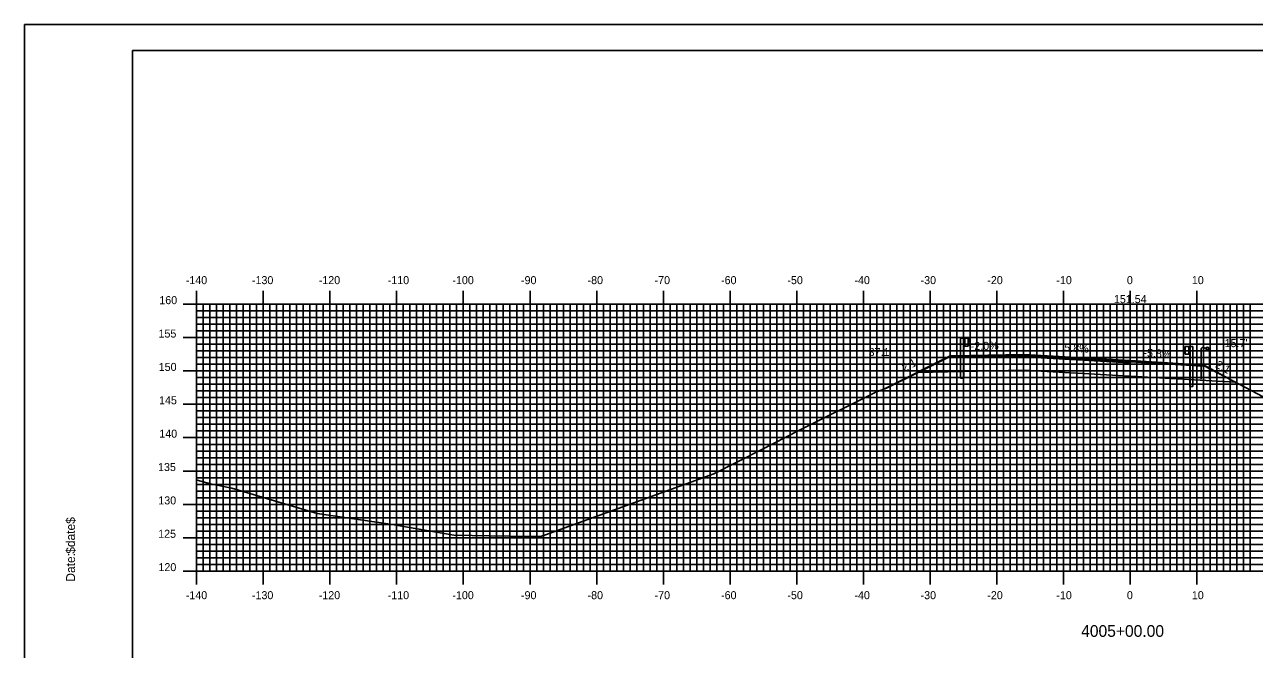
# Model space of a CAD drawing. Extents: x 850966 to 851310, y 364661 to 364881.
# Drawn here: x 850966.4 to 851150.9, y 364787.7 to 364881.3 of the extents above; entities that cross this region are included whole.
import ezdxf

# ---------------------------------------------------------------- set-up
doc = ezdxf.new("R2010")
doc.units = 0
for name, color, linetype in [('ANNOTATION', 7, 'Continuous'), ('BORDER', 7, 'Continuous'), ('D_Guardrail_Beam_Lt', 7, 'Continuous'), ('D_Guardrail_Beam_Rt', 7, 'Continuous'), ('D_Roadway_Centerline_Text', 7, 'Continuous'), ('D_Roadway_Edge_Shoulder', 7, 'Continuous'), ('D_Roadway_Edge_TW', 7, 'Continuous'), ('D_Roadway_Pavement', 7, 'Continuous'), ('D_Roadway_SlopeLines', 7, 'Continuous'), ('D_Roadway_SubGrade', 7, 'Continuous'), ('D_Text_Standard', 7, 'Continuous'), ('H_V ANNOTATION', 7, 'Continuous'), ('M_Roadway_Centerline', 7, 'Continuous'), ('M_Utilities_Pole_StreetLight', 7, 'Continuous'), ('MAJOR', 7, 'Continuous'), ('MINOR', 7, 'Continuous'), ('PLOT BOUNDARY', 7, 'Continuous'), ('S_Roadway_Centerline', 7, 'Continuous')]:
    doc.layers.add(name, color=color, linetype=linetype)

msp = doc.modelspace()

# ---------------------------------------------------------------- linework, layer by layer
at = {"layer": 'BORDER'}
msp.add_lwpolyline([(850982.62, 364667.37), (851302.62, 364667.37), (851302.62, 364877.37), (850982.62, 364877.37)], close=True, dxfattribs=at)
at = {"layer": 'D_Guardrail_Beam_Lt'}
for p, q in [((851106.79, 364834.26), (851106.79, 364828.26)), ((851107.26, 364834.26), (851106.79, 364834.26)), ((851107.94, 364834.26), (851107.26, 364834.26)), ((851107.26, 364834.26), (851107.26, 364833.09)), ((851107.32, 364834.26), (851107.32, 364833.09)), ((851107.42, 364834.26), (851107.42, 364833.09)), ((851107.94, 364833.09), (851107.94, 364834.26)), ((851107.94, 364834.18), (851108.02, 364834.16)), ((851107.95, 364833.71), (851107.95, 364833.64)), ((851108.18, 364833.91), (851107.98, 364833.78)), ((851108.03, 364834.16), (851108.18, 364834.06)), ((851107.26, 364833.09), (851107.94, 364833.09)), ((851107.28, 364828.26), (851107.28, 364833.09)), ((851108.02, 364833.19), (851107.94, 364833.18)), ((851107.98, 364833.58), (851108.18, 364833.44)), ((851108.18, 364833.3), (851108.03, 364833.2)), ((851107.28, 364828.26), (851106.79, 364828.26))]:
    msp.add_line(p, q, dxfattribs=at)
for centre, major_axis, start_param, end_param in [((851108.03, 364833.71), (-0.0789, 0), 5.323254, 6.283185), ((851108.03, 364833.64), (-0.0789, 0), 6.283185, 7.243116), ((851108.01, 364834.12), (0.0417, 0), 0.959931, 1.376053), ((851108.13, 364833.98), (0.0877, 0), 5.323254, 7.243116), ((851108.01, 364833.23), (0.0417, 0), 4.907132, 5.323254), ((851108.13, 364833.37), (0.0877, 0), 5.323254, 7.243116)]:
    msp.add_ellipse(centre, major_axis=major_axis, ratio=0.995501, start_param=start_param, end_param=end_param, dxfattribs=at)
at = {"layer": 'D_Guardrail_Beam_Rt'}
for p, q in [((851140.4, 364832.92), (851140.25, 364832.82)), ((851140.25, 364832.68), (851140.45, 364832.54)), ((851140.45, 364832.35), (851140.25, 364832.21)), ((851140.25, 364832.07), (851140.4, 364831.97)), ((851140.49, 364832.95), (851140.41, 364832.93)), ((851140.41, 364831.96), (851140.49, 364831.95)), ((851140.48, 364832.48), (851140.48, 364832.41)), ((851140.49, 364833.03), (851141.17, 364833.03)), ((851140.49, 364831.86), (851140.49, 364833.03)), ((851141.17, 364831.86), (851140.49, 364831.86)), ((851141.01, 364833.03), (851141.01, 364831.86)), ((851141.11, 364833.03), (851141.11, 364831.86)), ((851141.15, 364827.03), (851141.15, 364831.86)), ((851141.17, 364833.03), (851141.64, 364833.03)), ((851141.17, 364833.03), (851141.17, 364831.86)), ((851141.64, 364833.03), (851141.64, 364827.03)), ((851141.15, 364827.03), (851141.64, 364827.03))]:
    msp.add_line(p, q, dxfattribs=at)
for centre, major_axis, start_param, end_param in [((851140.3, 364832.75), (-0.0877, 0), 5.323254, 7.243116), ((851140.3, 364832.14), (-0.0877, 0), 5.323254, 7.243116), ((851140.42, 364832.89), (-0.0417, 0), 4.907132, 5.323254), ((851140.42, 364832), (-0.0417, 0), 0.959931, 1.376053), ((851140.4, 364832.48), (0.0789, 0), 0, 0.959931), ((851140.4, 364832.41), (0.0789, 0), 5.323254, 6.283185)]:
    msp.add_ellipse(centre, major_axis=major_axis, ratio=0.995501, start_param=start_param, end_param=end_param, dxfattribs=at)
at = {"layer": 'D_Roadway_Edge_Shoulder'}
for points in [[(851116.22, 364831.84), (851108.22, 364831.68), (851108.22, 364831.68), (851105.22, 364831.62), (851105.22, 364831.45), (851116.22, 364831.64)], [(851132.22, 364830.91), (851140.22, 364830.45), (851140.22, 364830.45), (851143.22, 364830.27), (851143.22, 364830.1), (851132.22, 364830.74)]]:
    msp.add_lwpolyline(points, close=True, dxfattribs=at)
at = {"layer": 'D_Roadway_Edge_TW'}
msp.add_lwpolyline([(851116.22, 364831.84), (851132.22, 364830.91), (851132.22, 364830.74), (851116.22, 364831.64)], close=True, dxfattribs=at)
at = {"layer": 'D_Roadway_Pavement'}
msp.add_lwpolyline([(851116.22, 364831.64), (851132.22, 364830.74), (851132.22, 364830.58), (851116.22, 364831.47)], close=True, dxfattribs=at)
for points in [[(851116.22, 364831.64), (851116.22, 364831.47)], [(851132.22, 364830.74), (851132.22, 364830.58)], [(851132.22, 364830.74), (851132.22, 364830.58)], [(851132.22, 364830.74), (851132.22, 364830.58)]]:
    msp.add_lwpolyline(points, dxfattribs=at)
at = {"layer": 'D_Roadway_SlopeLines'}
msp.add_lwpolyline([(851105.22, 364831.62), (851095.16, 364826.59)], dxfattribs=at)
at = {"layer": 'D_Roadway_SubGrade'}
msp.add_line((851143.22, 364830.27), (851147.95, 364827.69), dxfattribs=at)
for points in [[(851116.22, 364831.47), (851116.22, 364831.64), (851105.22, 364831.45), (851105.22, 364831.62), (851100.29, 364829.15), (851116.22, 364829.47)], [(851116.22, 364831.47), (851132.22, 364830.58), (851132.22, 364828.58), (851116.22, 364829.47)]]:
    msp.add_lwpolyline(points, close=True, dxfattribs=at)
msp.add_lwpolyline([(851147.95, 364827.69), (851132.22, 364828.58), (851132.22, 364830.58), (851132.22, 364830.74), (851143.22, 364830.1), (851143.22, 364830.27)], dxfattribs=at)
at = {"layer": 'M_Utilities_Pole_StreetLight'}
for p, q in [((851142.87, 364832.75), (851143.03, 364832.86)), ((851142.87, 364828.13), (851142.87, 364832.75)), ((851143.34, 364832.86), (851143.49, 364832.75)), ((851143.65, 364832.86), (851143.49, 364832.75)), ((851143.49, 364832.75), (851143.65, 364832.64)), ((851144.12, 364832.75), (851143.96, 364832.86)), ((851143.96, 364832.64), (851144.12, 364832.75)), ((851144.12, 364828.13), (851144.12, 364832.75))]:
    msp.add_line(p, q, dxfattribs=at)
for centre, start, end in [((851143.18, 364832.64), 90, 125.2644), ((851143.18, 364832.64), 54.7356, 90), ((851143.81, 364832.64), 90, 125.2644), ((851143.81, 364832.86), 234.7356, 270), ((851143.81, 364832.64), 54.7356, 90), ((851143.81, 364832.86), 270, 305.2644)]:
    msp.add_arc(centre, 0.271, start, end, dxfattribs=at)
at = {"layer": 'MAJOR'}
for p, q in [((850992.22, 364841.37), (850992.22, 364839.37)), ((851002.22, 364841.37), (851002.22, 364839.37)), ((851012.22, 364841.37), (851012.22, 364839.37)), ((851022.22, 364841.37), (851022.22, 364839.37)), ((851032.22, 364841.37), (851032.22, 364839.37)), ((851042.22, 364841.37), (851042.22, 364839.37)), ((851052.22, 364841.37), (851052.22, 364839.37)), ((851062.22, 364841.37), (851062.22, 364839.37)), ((851072.22, 364841.37), (851072.22, 364839.37)), ((851082.22, 364841.37), (851082.22, 364839.37)), ((851092.22, 364841.37), (851092.22, 364839.37)), ((851102.22, 364841.37), (851102.22, 364839.37)), ((851112.22, 364841.37), (851112.22, 364839.37)), ((851122.22, 364841.37), (851122.22, 364839.37)), ((851132.22, 364841.37), (851132.22, 364839.37)), ((851142.22, 364841.37), (851142.22, 364839.37)), ((850990.21, 364839.37), (850992.22, 364839.37)), ((850992.22, 364839.37), (851272.22, 364839.37)), ((850992.22, 364799.37), (850992.22, 364839.37)), ((850992.22, 364799.37), (850992.22, 364839.37)), ((850992.22, 364839.37), (851272.22, 364839.37)), ((851002.22, 364799.37), (851002.22, 364839.37)), ((851012.22, 364799.37), (851012.22, 364839.37)), ((851022.22, 364799.37), (851022.22, 364839.37)), ((851032.22, 364799.37), (851032.22, 364839.37)), ((851042.22, 364799.37), (851042.22, 364839.37)), ((851052.22, 364799.37), (851052.22, 364839.37)), ((851062.22, 364799.37), (851062.22, 364839.37)), ((851072.22, 364799.37), (851072.22, 364839.37)), ((851082.22, 364799.37), (851082.22, 364839.37)), ((851092.22, 364799.37), (851092.22, 364839.37)), ((851102.22, 364799.37), (851102.22, 364839.37)), ((851112.22, 364799.37), (851112.22, 364839.37)), ((851122.22, 364799.37), (851122.22, 364839.37)), ((851132.22, 364799.37), (851132.22, 364839.37)), ((851142.22, 364799.37), (851142.22, 364839.37)), ((850990.21, 364834.37), (850992.22, 364834.37)), ((850992.22, 364834.37), (851272.22, 364834.37)), ((850990.21, 364829.37), (850992.22, 364829.37)), ((850992.22, 364829.37), (851272.22, 364829.37)), ((850990.21, 364824.37), (850992.22, 364824.37)), ((850992.22, 364824.37), (851272.22, 364824.37)), ((850990.21, 364819.37), (850992.22, 364819.37)), ((850992.22, 364819.37), (851272.22, 364819.37)), ((850990.21, 364814.37), (850992.22, 364814.37)), ((850992.22, 364814.37), (851272.22, 364814.37)), ((850990.21, 364809.37), (850992.22, 364809.37)), ((850992.22, 364809.37), (851272.22, 364809.37)), ((850990.21, 364804.37), (850992.22, 364804.37)), ((850992.22, 364804.37), (851272.22, 364804.37)), ((850990.21, 364799.37), (850992.22, 364799.37)), ((850992.22, 364799.37), (851272.22, 364799.37)), ((850992.22, 364799.37), (851272.22, 364799.37)), ((850992.22, 364797.37), (850992.22, 364799.37)), ((851002.22, 364797.37), (851002.22, 364799.37)), ((851012.22, 364797.37), (851012.22, 364799.37)), ((851022.22, 364797.37), (851022.22, 364799.37)), ((851032.22, 364797.37), (851032.22, 364799.37)), ((851042.22, 364797.37), (851042.22, 364799.37)), ((851052.22, 364797.37), (851052.22, 364799.37)), ((851062.22, 364797.37), (851062.22, 364799.37)), ((851072.22, 364797.37), (851072.22, 364799.37)), ((851082.22, 364797.37), (851082.22, 364799.37)), ((851092.22, 364797.37), (851092.22, 364799.37)), ((851102.22, 364797.37), (851102.22, 364799.37)), ((851112.22, 364797.37), (851112.22, 364799.37)), ((851122.22, 364797.37), (851122.22, 364799.37)), ((851132.22, 364797.37), (851132.22, 364799.37)), ((851142.22, 364797.37), (851142.22, 364799.37))]:
    msp.add_line(p, q, dxfattribs=at)
at = {"layer": 'MINOR'}
for p, q in [((850993.22, 364799.37), (850993.22, 364839.37)), ((850994.22, 364799.37), (850994.22, 364839.37)), ((850995.22, 364799.37), (850995.22, 364839.37)), ((850996.22, 364799.37), (850996.22, 364839.37)), ((850997.22, 364799.37), (850997.22, 364839.37)), ((850998.22, 364799.37), (850998.22, 364839.37)), ((850999.22, 364799.37), (850999.22, 364839.37)), ((851000.22, 364799.37), (851000.22, 364839.37)), ((851001.22, 364799.37), (851001.22, 364839.37)), ((851003.22, 364799.37), (851003.22, 364839.37)), ((851004.22, 364799.37), (851004.22, 364839.37)), ((851005.22, 364799.37), (851005.22, 364839.37)), ((851006.22, 364799.37), (851006.22, 364839.37)), ((851007.22, 364799.37), (851007.22, 364839.37)), ((851008.22, 364799.37), (851008.22, 364839.37)), ((851009.22, 364799.37), (851009.22, 364839.37)), ((851010.22, 364799.37), (851010.22, 364839.37)), ((851011.22, 364799.37), (851011.22, 364839.37)), ((851013.22, 364799.37), (851013.22, 364839.37)), ((851014.22, 364799.37), (851014.22, 364839.37)), ((851015.22, 364799.37), (851015.22, 364839.37)), ((851016.22, 364799.37), (851016.22, 364839.37)), ((851017.22, 364799.37), (851017.22, 364839.37)), ((851018.22, 364799.37), (851018.22, 364839.37)), ((851019.22, 364799.37), (851019.22, 364839.37)), ((851020.22, 364799.37), (851020.22, 364839.37)), ((851021.22, 364799.37), (851021.22, 364839.37)), ((851023.22, 364799.37), (851023.22, 364839.37)), ((851024.22, 364799.37), (851024.22, 364839.37)), ((851025.22, 364799.37), (851025.22, 364839.37)), ((851026.22, 364799.37), (851026.22, 364839.37)), ((851027.22, 364799.37), (851027.22, 364839.37)), ((851028.22, 364799.37), (851028.22, 364839.37)), ((851029.22, 364799.37), (851029.22, 364839.37)), ((851030.22, 364799.37), (851030.22, 364839.37)), ((851031.22, 364799.37), (851031.22, 364839.37)), ((851033.22, 364799.37), (851033.22, 364839.37)), ((851034.22, 364799.37), (851034.22, 364839.37)), ((851035.22, 364799.37), (851035.22, 364839.37)), ((851036.22, 364799.37), (851036.22, 364839.37)), ((851037.22, 364799.37), (851037.22, 364839.37)), ((851038.22, 364799.37), (851038.22, 364839.37)), ((851039.22, 364799.37), (851039.22, 364839.37)), ((851040.22, 364799.37), (851040.22, 364839.37)), ((851041.22, 364799.37), (851041.22, 364839.37)), ((851043.22, 364799.37), (851043.22, 364839.37)), ((851044.22, 364799.37), (851044.22, 364839.37)), ((851045.22, 364799.37), (851045.22, 364839.37)), ((851046.22, 364799.37), (851046.22, 364839.37)), ((851047.22, 364799.37), (851047.22, 364839.37)), ((851048.22, 364799.37), (851048.22, 364839.37)), ((851049.22, 364799.37), (851049.22, 364839.37)), ((851050.22, 364799.37), (851050.22, 364839.37)), ((851051.22, 364799.37), (851051.22, 364839.37)), ((851053.22, 364799.37), (851053.22, 364839.37)), ((851054.22, 364799.37), (851054.22, 364839.37)), ((851055.22, 364799.37), (851055.22, 364839.37)), ((851056.22, 364799.37), (851056.22, 364839.37)), ((851057.22, 364799.37), (851057.22, 364839.37)), ((851058.22, 364799.37), (851058.22, 364839.37)), ((851059.22, 364799.37), (851059.22, 364839.37)), ((851060.22, 364799.37), (851060.22, 364839.37)), ((851061.22, 364799.37), (851061.22, 364839.37)), ((851063.22, 364799.37), (851063.22, 364839.37)), ((851064.22, 364799.37), (851064.22, 364839.37)), ((851065.22, 364799.37), (851065.22, 364839.37)), ((851066.22, 364799.37), (851066.22, 364839.37)), ((851067.22, 364799.37), (851067.22, 364839.37)), ((851068.22, 364799.37), (851068.22, 364839.37)), ((851069.22, 364799.37), (851069.22, 364839.37)), ((851070.22, 364799.37), (851070.22, 364839.37)), ((851071.22, 364799.37), (851071.22, 364839.37)), ((851073.22, 364799.37), (851073.22, 364839.37)), ((851074.22, 364799.37), (851074.22, 364839.37)), ((851075.22, 364799.37), (851075.22, 364839.37)), ((851076.22, 364799.37), (851076.22, 364839.37)), ((851077.22, 364799.37), (851077.22, 364839.37)), ((851078.22, 364799.37), (851078.22, 364839.37)), ((851079.22, 364799.37), (851079.22, 364839.37)), ((851080.22, 364799.37), (851080.22, 364839.37)), ((851081.22, 364799.37), (851081.22, 364839.37)), ((851083.22, 364799.37), (851083.22, 364839.37)), ((851084.22, 364799.37), (851084.22, 364839.37)), ((851085.22, 364799.37), (851085.22, 364839.37)), ((851086.22, 364799.37), (851086.22, 364839.37)), ((851087.22, 364799.37), (851087.22, 364839.37)), ((851088.22, 364799.37), (851088.22, 364839.37)), ((851089.22, 364799.37), (851089.22, 364839.37)), ((851090.22, 364799.37), (851090.22, 364839.37)), ((851091.22, 364799.37), (851091.22, 364839.37)), ((851093.22, 364799.37), (851093.22, 364839.37)), ((851094.22, 364799.37), (851094.22, 364839.37)), ((851095.22, 364799.37), (851095.22, 364839.37)), ((851096.22, 364799.37), (851096.22, 364839.37)), ((851097.22, 364799.37), (851097.22, 364839.37)), ((851098.22, 364799.37), (851098.22, 364839.37)), ((851099.22, 364799.37), (851099.22, 364839.37)), ((851100.22, 364799.37), (851100.22, 364839.37)), ((851101.22, 364799.37), (851101.22, 364839.37)), ((851103.22, 364799.37), (851103.22, 364839.37)), ((851104.22, 364799.37), (851104.22, 364839.37)), ((851105.22, 364799.37), (851105.22, 364839.37)), ((851106.22, 364799.37), (851106.22, 364839.37)), ((851107.22, 364799.37), (851107.22, 364839.37)), ((851108.22, 364799.37), (851108.22, 364839.37)), ((851109.22, 364799.37), (851109.22, 364839.37)), ((851110.22, 364799.37), (851110.22, 364839.37)), ((851111.22, 364799.37), (851111.22, 364839.37)), ((851113.22, 364799.37), (851113.22, 364839.37)), ((851114.22, 364799.37), (851114.22, 364839.37)), ((851115.22, 364799.37), (851115.22, 364839.37)), ((851116.22, 364799.37), (851116.22, 364839.37)), ((851117.22, 364799.37), (851117.22, 364839.37)), ((851118.22, 364799.37), (851118.22, 364839.37)), ((851119.22, 364799.37), (851119.22, 364839.37)), ((851120.22, 364799.37), (851120.22, 364839.37)), ((851121.22, 364799.37), (851121.22, 364839.37)), ((851123.22, 364799.37), (851123.22, 364839.37)), ((851124.22, 364799.37), (851124.22, 364839.37)), ((851125.22, 364799.37), (851125.22, 364839.37)), ((851126.22, 364799.37), (851126.22, 364839.37)), ((851127.22, 364799.37), (851127.22, 364839.37)), ((851128.22, 364799.37), (851128.22, 364839.37)), ((851129.22, 364799.37), (851129.22, 364839.37)), ((851130.22, 364799.37), (851130.22, 364839.37)), ((851131.22, 364799.37), (851131.22, 364839.37)), ((851133.22, 364799.37), (851133.22, 364839.37)), ((851134.22, 364799.37), (851134.22, 364839.37)), ((851135.22, 364799.37), (851135.22, 364839.37)), ((851136.22, 364799.37), (851136.22, 364839.37)), ((851137.22, 364799.37), (851137.22, 364839.37)), ((851138.22, 364799.37), (851138.22, 364839.37)), ((851139.22, 364799.37), (851139.22, 364839.37)), ((851140.22, 364799.37), (851140.22, 364839.37)), ((851141.22, 364799.37), (851141.22, 364839.37)), ((851143.22, 364799.37), (851143.22, 364839.37)), ((851144.22, 364799.37), (851144.22, 364839.37)), ((851145.22, 364799.37), (851145.22, 364839.37)), ((851146.22, 364799.37), (851146.22, 364839.37)), ((851147.22, 364799.37), (851147.22, 364839.37)), ((851148.22, 364799.37), (851148.22, 364839.37)), ((851149.22, 364799.37), (851149.22, 364839.37)), ((851150.22, 364799.37), (851150.22, 364839.37)), ((850992.22, 364838.37), (851272.22, 364838.37)), ((850992.22, 364838.37), (850994.22, 364838.37)), ((850992.22, 364837.37), (851272.22, 364837.37)), ((850992.22, 364837.37), (850994.22, 364837.37)), ((850992.22, 364836.37), (851272.22, 364836.37)), ((850992.22, 364836.37), (850994.22, 364836.37)), ((850992.22, 364835.37), (851272.22, 364835.37)), ((850992.22, 364835.37), (850994.22, 364835.37)), ((850992.22, 364833.37), (851272.22, 364833.37)), ((850992.22, 364833.37), (850994.22, 364833.37)), ((850992.22, 364832.37), (851272.22, 364832.37)), ((850992.22, 364832.37), (850994.22, 364832.37)), ((850992.22, 364831.37), (851272.22, 364831.37)), ((850992.22, 364831.37), (850994.22, 364831.37)), ((850992.22, 364830.37), (851272.22, 364830.37)), ((850992.22, 364830.37), (850994.22, 364830.37)), ((850992.22, 364828.37), (851272.22, 364828.37)), ((850992.22, 364828.37), (850994.22, 364828.37)), ((850992.22, 364827.37), (851272.22, 364827.37)), ((850992.22, 364827.37), (850994.22, 364827.37)), ((850992.22, 364826.37), (851272.22, 364826.37)), ((850992.22, 364826.37), (850994.22, 364826.37)), ((850992.22, 364825.37), (851272.22, 364825.37)), ((850992.22, 364825.37), (850994.22, 364825.37)), ((850992.22, 364823.37), (851272.22, 364823.37)), ((850992.22, 364823.37), (850994.22, 364823.37)), ((850992.22, 364822.37), (851272.22, 364822.37)), ((850992.22, 364822.37), (850994.22, 364822.37)), ((850992.22, 364821.37), (851272.22, 364821.37)), ((850992.22, 364821.37), (850994.22, 364821.37)), ((850992.22, 364820.37), (851272.22, 364820.37)), ((850992.22, 364820.37), (850994.22, 364820.37)), ((850992.22, 364818.37), (851272.22, 364818.37)), ((850992.22, 364818.37), (850994.22, 364818.37)), ((850992.22, 364817.37), (851272.22, 364817.37)), ((850992.22, 364817.37), (850994.22, 364817.37)), ((850992.22, 364816.37), (851272.22, 364816.37)), ((850992.22, 364816.37), (850994.22, 364816.37)), ((850992.22, 364815.37), (851272.22, 364815.37)), ((850992.22, 364815.37), (850994.22, 364815.37)), ((850992.22, 364813.37), (851272.22, 364813.37)), ((850992.22, 364813.37), (850994.22, 364813.37)), ((850992.22, 364812.37), (851272.22, 364812.37)), ((850992.22, 364812.37), (850994.22, 364812.37)), ((850992.22, 364811.37), (851272.22, 364811.37)), ((850992.22, 364811.37), (850994.22, 364811.37)), ((850992.22, 364810.37), (851272.22, 364810.37)), ((850992.22, 364810.37), (850994.22, 364810.37)), ((850992.22, 364808.37), (851272.22, 364808.37)), ((850992.22, 364808.37), (850994.22, 364808.37)), ((850992.22, 364807.37), (851272.22, 364807.37)), ((850992.22, 364807.37), (850994.22, 364807.37)), ((850992.22, 364806.37), (851272.22, 364806.37)), ((850992.22, 364806.37), (850994.22, 364806.37)), ((850992.22, 364805.37), (851272.22, 364805.37)), ((850992.22, 364805.37), (850994.22, 364805.37)), ((850992.22, 364803.37), (851272.22, 364803.37)), ((850992.22, 364803.37), (850994.22, 364803.37)), ((850992.22, 364802.37), (851272.22, 364802.37)), ((850992.22, 364802.37), (850994.22, 364802.37)), ((850992.22, 364801.37), (851272.22, 364801.37)), ((850992.22, 364801.37), (850994.22, 364801.37)), ((850992.22, 364800.37), (851272.22, 364800.37)), ((850992.22, 364800.37), (850994.22, 364800.37))]:
    msp.add_line(p, q, dxfattribs=at)
at = {"layer": 'PLOT BOUNDARY'}
msp.add_lwpolyline([(850966.43, 364661.25), (851306.43, 364661.25), (851306.43, 364881.25), (850966.43, 364881.25)], close=True, dxfattribs=at)
at = {"layer": 'S_Roadway_Centerline'}
for points in [[(851095.7, 364826.78), (851100.01, 364828.93), (851105.22, 364831.53), (851108.22, 364831.59), (851116.22, 364831.75), (851132.22, 364830.83), (851140.22, 364830.36), (851143.22, 364830.19), (851148.55, 364827.38), (851175.19, 364813.36)], [(850992.22, 364813.05), (850992.32, 364813.01), (850994.33, 364812.43), (850997.53, 364811.79), (851010.29, 364808), (851021.25, 364806.43), (851030.78, 364804.77), (851041.83, 364804.54), (851043.79, 364804.57), (851044.55, 364804.83), (851069.79, 364813.94), (851076.89, 364817.55), (851082.52, 364820.44), (851094.07, 364826.21), (851095.7, 364826.78)]]:
    msp.add_lwpolyline(points, dxfattribs=at)

# ---------------------------------------------------------------- texts
at = {"layer": 'ANNOTATION'}
for s, rotation, p in [('-2.0%', 1.1458, (851108.32, 364832.48)), ('5.8%', 356.6806, (851122.32, 364832.29)), ('-5.8%', 356.6806, (851134.19, 364831.52)), ('2:1', 26.5651, (851098.33, 364829.21)), ('2:1', 331.4585, (851144.9, 364829.96))]:
    msp.add_text(s, height=1.2, rotation=rotation, dxfattribs=at).set_placement(p)
at = {"layer": 'BORDER'}
for s, p in [('$date$', (850973.99, 364801.98)), ('Date:', (850973.99, 364797.8))]:
    msp.add_text(s, height=1.339, rotation=90, dxfattribs=at).set_placement(p)
at = {"layer": 'D_Roadway_Centerline_Text'}
msp.add_text('151.54', height=1.2, dxfattribs=at).set_placement((851129.78, 364839.53))
at = {"layer": 'D_Text_Standard'}
for s, p in [("15.7'", (851146.38, 364832.93)), ("37.1'", (851093, 364831.6))]:
    msp.add_text(s, height=1.2, dxfattribs=at).set_placement(p)
at = {"layer": 'H_V ANNOTATION'}
for s, height, p in [('-140', 1.2, (850990.6, 364842.37)), ('-130', 1.2, (851000.52, 364842.37)), ('-120', 1.2, (851010.54, 364842.37)), ('-110', 1.2, (851020.88, 364842.37)), ('-100', 1.2, (851030.58, 364842.37)), ('-90', 1.2, (851040.87, 364842.37)), ('-80', 1.2, (851050.85, 364842.37)), ('-70', 1.2, (851060.9, 364842.37)), ('-60', 1.2, (851070.87, 364842.37)), ('-50', 1.2, (851080.82, 364842.37)), ('-40', 1.2, (851090.87, 364842.37)), ('-30', 1.2, (851100.79, 364842.37)), ('-20', 1.2, (851110.8, 364842.37)), ('-10', 1.2, (851121.15, 364842.37)), ('0', 1.2, (851131.73, 364842.37)), ('10', 1.2, (851141.47, 364842.37)), ('160', 1.2, (850986.63, 364839.37)), ('155', 1.2, (850986.51, 364834.37)), ('150', 1.2, (850986.54, 364829.37)), ('145', 1.2, (850986.59, 364824.37)), ('140', 1.2, (850986.63, 364819.37)), ('135', 1.2, (850986.44, 364814.37)), ('130', 1.2, (850986.48, 364809.37)), ('125', 1.2, (850986.46, 364804.37)), ('120', 1.2, (850986.5, 364799.37)), ('-140', 1.2, (850990.6, 364795.17)), ('-130', 1.2, (851000.52, 364795.17)), ('-120', 1.2, (851010.54, 364795.17)), ('-110', 1.2, (851020.88, 364795.17)), ('-100', 1.2, (851030.58, 364795.17)), ('-90', 1.2, (851040.87, 364795.17)), ('-80', 1.2, (851050.85, 364795.17)), ('-70', 1.2, (851060.9, 364795.17)), ('-60', 1.2, (851070.87, 364795.17)), ('-50', 1.2, (851080.82, 364795.17)), ('-40', 1.2, (851090.87, 364795.17)), ('-30', 1.2, (851100.79, 364795.17)), ('-20', 1.2, (851110.8, 364795.17)), ('-10', 1.2, (851121.15, 364795.17)), ('0', 1.2, (851131.73, 364795.17)), ('10', 1.2, (851141.47, 364795.17)), ('4005+00.00', 1.75, (851124.87, 364789.53))]:
    msp.add_text(s, height=height, dxfattribs=at).set_placement(p)
at = {"layer": 'M_Roadway_Centerline'}
for s, p in [('C', (851120.38, 364829.87)), ('L', (851120.38, 364829.86))]:
    msp.add_text(s, height=0.0146, dxfattribs=at).set_placement(p)
at = {"layer": 'MAJOR'}
msp.add_text('-', height=0.012, dxfattribs=at).set_placement((850992.21, 364799.37))

doc.saveas('drawing.dxf')
